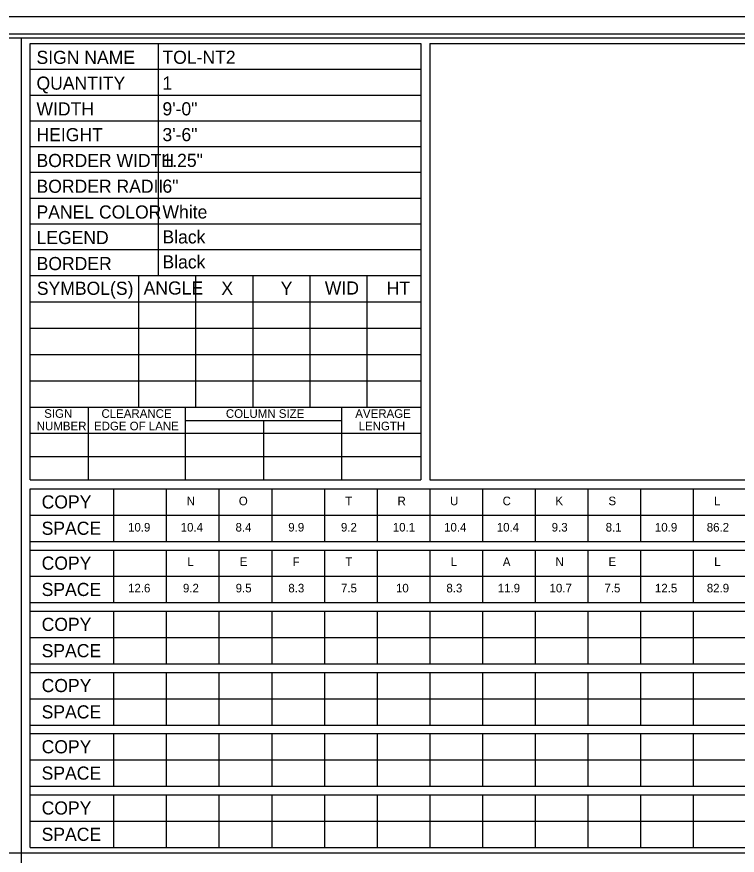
# Model space of a CAD drawing. Extents: x 17890628 to 17890844, y 17897508 to 17897992.
# Drawn here: x 17890772.14 to 17890808.72, y 17897557.55 to 17897600.12 of the extents above; entities that cross this region are included whole.
import ezdxf

# ---------------------------------------------------------------- set-up
doc = ezdxf.new("R2010")
doc.units = 0
for name, color, linetype in [('GSSign', 7, 'Continuous'), ('PlotBorder_dp', 7, 'Continuous'), ('SheetBorder_dp', 7, 'Continuous'), ('SheetLinesMisc2_dp', 7, 'Continuous'), ('TextMinor', 7, 'Continuous')]:
    doc.layers.add(name, color=color, linetype=linetype)

msp = doc.modelspace()

# ---------------------------------------------------------------- linework, layer by layer
at = {"layer": 'PlotBorder_dp'}
msp.add_lwpolyline([(17890700.471, 17897507.741), (17890844.259, 17897507.741), (17890844.259, 17897600.116), (17890700.471, 17897600.116)], close=True, dxfattribs=at)
at = {"layer": 'SheetBorder_dp'}
msp.add_line((17890705.263, 17897599.245), (17890839.466, 17897599.245), dxfattribs=at)
at = {"layer": 'SheetLinesMisc2_dp'}
for p, q in [((17890705.5, 17897599.039), (17890839.233, 17897599.039)), ((17890772.367, 17897599.039), (17890772.367, 17897515.791)), ((17890772.823, 17897576.606), (17890772.823, 17897598.762)), ((17890772.823, 17897598.762), (17890792.654, 17897598.762)), ((17890779.324, 17897598.762), (17890779.324, 17897586.981)), ((17890792.654, 17897598.762), (17890792.654, 17897576.606)), ((17890793.11, 17897598.762), (17890838.594, 17897598.762)), ((17890793.11, 17897598.762), (17890793.11, 17897576.606)), ((17890772.823, 17897597.453), (17890792.654, 17897597.453)), ((17890772.823, 17897596.144), (17890792.654, 17897596.144)), ((17890772.823, 17897594.836), (17890792.654, 17897594.836)), ((17890772.823, 17897593.527), (17890792.654, 17897593.527)), ((17890772.823, 17897592.218), (17890792.654, 17897592.218)), ((17890772.823, 17897590.91), (17890792.654, 17897590.91)), ((17890772.823, 17897589.601), (17890782.738, 17897589.601)), ((17890782.738, 17897589.601), (17890792.654, 17897589.601)), ((17890772.823, 17897588.293), (17890782.738, 17897588.293)), ((17890782.738, 17897588.293), (17890792.654, 17897588.293)), ((17890772.823, 17897586.981), (17890792.654, 17897586.981)), ((17890778.326, 17897586.981), (17890778.326, 17897580.3)), ((17890781.223, 17897586.981), (17890781.223, 17897580.3)), ((17890784.121, 17897586.981), (17890784.121, 17897580.3)), ((17890787.019, 17897586.981), (17890787.019, 17897580.3)), ((17890789.916, 17897586.981), (17890789.916, 17897580.3)), ((17890772.823, 17897585.645), (17890792.654, 17897585.645)), ((17890772.823, 17897584.308), (17890792.654, 17897584.308)), ((17890772.823, 17897582.972), (17890792.654, 17897582.972)), ((17890772.823, 17897581.636), (17890792.654, 17897581.636)), ((17890772.823, 17897580.3), (17890792.654, 17897580.3)), ((17890775.761, 17897580.3), (17890775.761, 17897576.607)), ((17890780.696, 17897580.3), (17890780.696, 17897576.607)), ((17890788.628, 17897580.3), (17890788.628, 17897576.607)), ((17890780.696, 17897579.619), (17890788.628, 17897579.619)), ((17890784.663, 17897579.619), (17890784.663, 17897576.607)), ((17890772.823, 17897578.98), (17890792.654, 17897578.98)), ((17890772.823, 17897577.793), (17890792.654, 17897577.793)), ((17890772.823, 17897576.606), (17890792.654, 17897576.606)), ((17890793.11, 17897576.606), (17890838.594, 17897576.606)), ((17890772.824, 17897557.939), (17890772.824, 17897576.15)), ((17890772.824, 17897576.15), (17890838.594, 17897576.15)), ((17890777.058, 17897576.15), (17890777.058, 17897573.478)), ((17890779.733, 17897576.15), (17890779.733, 17897573.478)), ((17890782.408, 17897576.15), (17890782.408, 17897573.478)), ((17890785.084, 17897576.15), (17890785.084, 17897573.478)), ((17890787.76, 17897576.15), (17890787.76, 17897573.478)), ((17890790.435, 17897576.15), (17890790.435, 17897573.478)), ((17890793.11, 17897576.15), (17890793.11, 17897573.478)), ((17890795.786, 17897576.15), (17890795.786, 17897573.478)), ((17890798.462, 17897576.15), (17890798.462, 17897573.478)), ((17890801.137, 17897576.15), (17890801.137, 17897573.478)), ((17890803.813, 17897576.15), (17890803.813, 17897573.478)), ((17890806.488, 17897576.15), (17890806.488, 17897573.478)), ((17890772.824, 17897574.814), (17890838.594, 17897574.814)), ((17890772.824, 17897573.478), (17890838.594, 17897573.478)), ((17890772.824, 17897573.042), (17890838.594, 17897573.042)), ((17890777.058, 17897573.042), (17890777.058, 17897570.37)), ((17890779.733, 17897573.042), (17890779.733, 17897570.37)), ((17890782.408, 17897573.042), (17890782.408, 17897570.37)), ((17890785.084, 17897573.042), (17890785.084, 17897570.37)), ((17890787.76, 17897573.042), (17890787.76, 17897570.37)), ((17890790.435, 17897573.042), (17890790.435, 17897570.37)), ((17890793.11, 17897573.042), (17890793.11, 17897570.37)), ((17890795.786, 17897573.042), (17890795.786, 17897570.37)), ((17890798.462, 17897573.042), (17890798.462, 17897570.37)), ((17890801.137, 17897573.042), (17890801.137, 17897570.37)), ((17890803.813, 17897573.042), (17890803.813, 17897570.37)), ((17890806.488, 17897573.042), (17890806.488, 17897570.37)), ((17890772.824, 17897571.706), (17890838.594, 17897571.706)), ((17890772.824, 17897570.37), (17890838.594, 17897570.37)), ((17890772.824, 17897569.935), (17890838.594, 17897569.935)), ((17890777.058, 17897569.935), (17890777.058, 17897567.263)), ((17890779.733, 17897569.935), (17890779.733, 17897567.263)), ((17890782.408, 17897569.935), (17890782.408, 17897567.263)), ((17890785.084, 17897569.935), (17890785.084, 17897567.263)), ((17890787.76, 17897569.935), (17890787.76, 17897567.263)), ((17890790.435, 17897569.935), (17890790.435, 17897567.263)), ((17890793.11, 17897569.935), (17890793.11, 17897567.263)), ((17890795.786, 17897569.935), (17890795.786, 17897567.263)), ((17890798.462, 17897569.935), (17890798.462, 17897567.263)), ((17890801.137, 17897569.935), (17890801.137, 17897567.263)), ((17890803.813, 17897569.935), (17890803.813, 17897567.263)), ((17890806.488, 17897569.935), (17890806.488, 17897567.263)), ((17890772.824, 17897568.598), (17890838.594, 17897568.598)), ((17890772.824, 17897567.263), (17890838.594, 17897567.263)), ((17890772.824, 17897566.827), (17890838.594, 17897566.827)), ((17890777.058, 17897566.827), (17890777.058, 17897564.154)), ((17890779.733, 17897566.827), (17890779.733, 17897564.154)), ((17890782.408, 17897566.827), (17890782.408, 17897564.154)), ((17890785.084, 17897566.827), (17890785.084, 17897564.154)), ((17890787.76, 17897566.827), (17890787.76, 17897564.154)), ((17890790.435, 17897566.827), (17890790.435, 17897564.154)), ((17890793.11, 17897566.827), (17890793.11, 17897564.154)), ((17890795.786, 17897566.827), (17890795.786, 17897564.154)), ((17890798.462, 17897566.827), (17890798.462, 17897564.154)), ((17890801.137, 17897566.827), (17890801.137, 17897564.154)), ((17890803.813, 17897566.827), (17890803.813, 17897564.154)), ((17890806.488, 17897566.827), (17890806.488, 17897564.154)), ((17890772.824, 17897565.49), (17890838.594, 17897565.49)), ((17890772.824, 17897564.154), (17890838.594, 17897564.154)), ((17890772.824, 17897563.719), (17890838.594, 17897563.719)), ((17890777.058, 17897563.719), (17890777.058, 17897561.047)), ((17890779.733, 17897563.719), (17890779.733, 17897561.047)), ((17890782.408, 17897563.719), (17890782.408, 17897561.047)), ((17890785.084, 17897563.719), (17890785.084, 17897561.047)), ((17890787.76, 17897563.719), (17890787.76, 17897561.047)), ((17890790.435, 17897563.719), (17890790.435, 17897561.047)), ((17890793.11, 17897563.719), (17890793.11, 17897561.047)), ((17890795.786, 17897563.719), (17890795.786, 17897561.047)), ((17890798.462, 17897563.719), (17890798.462, 17897561.047)), ((17890801.137, 17897563.719), (17890801.137, 17897561.047)), ((17890803.813, 17897563.719), (17890803.813, 17897561.047)), ((17890806.488, 17897563.719), (17890806.488, 17897561.047)), ((17890772.824, 17897562.383), (17890838.594, 17897562.383)), ((17890772.824, 17897561.047), (17890838.594, 17897561.047)), ((17890772.824, 17897560.611), (17890838.594, 17897560.611)), ((17890777.058, 17897560.611), (17890777.058, 17897557.939)), ((17890779.733, 17897560.611), (17890779.733, 17897557.939)), ((17890782.408, 17897560.611), (17890782.408, 17897557.939)), ((17890785.084, 17897560.611), (17890785.084, 17897557.939)), ((17890787.76, 17897560.611), (17890787.76, 17897557.939)), ((17890790.435, 17897560.611), (17890790.435, 17897557.939)), ((17890793.11, 17897560.611), (17890793.11, 17897557.939)), ((17890795.786, 17897560.611), (17890795.786, 17897557.939)), ((17890798.462, 17897560.611), (17890798.462, 17897557.939)), ((17890801.137, 17897560.611), (17890801.137, 17897557.939)), ((17890803.813, 17897560.611), (17890803.813, 17897557.939)), ((17890806.488, 17897560.611), (17890806.488, 17897557.939)), ((17890772.824, 17897559.276), (17890838.594, 17897559.276)), ((17890772.824, 17897557.939), (17890838.594, 17897557.939)), ((17890705.5, 17897557.675), (17890839.233, 17897557.675))]:
    msp.add_line(p, q, dxfattribs=at)

# ---------------------------------------------------------------- texts
at = {"layer": 'GSSign'}
for s, height, p in [('TOL-NT2', 0.6667, (17890779.538, 17897597.727)), ('1', 0.667, (17890779.538, 17897596.418)), ('9\'-0"', 0.6667, (17890779.538, 17897595.109)), ('3\'-6"', 0.6667, (17890779.538, 17897593.801)), ('1.25"', 0.6667, (17890779.538, 17897592.492)), ('6"', 0.6667, (17890779.538, 17897591.183)), ('White', 0.6667, (17890779.538, 17897589.875)), ('Black', 0.6667, (17890779.538, 17897588.606)), ('Black', 0.6667, (17890779.538, 17897587.337)), ('N', 0.436, (17890780.765, 17897575.316)), ('O', 0.436, (17890783.416, 17897575.316)), ('T', 0.436, (17890788.819, 17897575.316)), ('R', 0.436, (17890791.473, 17897575.316)), ('U', 0.436, (17890794.142, 17897575.316)), ('C', 0.436, (17890796.809, 17897575.316)), ('K', 0.436, (17890799.489, 17897575.316)), ('S', 0.436, (17890802.185, 17897575.316)), ('L', 0.436, (17890807.549, 17897575.316)), ('10.9', 0.4357, (17890777.789, 17897573.98)), ('10.4', 0.4357, (17890780.462, 17897573.98)), ('8.4', 0.4357, (17890783.248, 17897573.98)), ('9.9', 0.4357, (17890785.925, 17897573.98)), ('9.2', 0.4357, (17890788.6, 17897573.98)), ('10.1', 0.4357, (17890791.232, 17897573.98)), ('10.4', 0.4357, (17890793.839, 17897573.98)), ('10.4', 0.4357, (17890796.514, 17897573.98)), ('9.3', 0.4357, (17890799.302, 17897573.98)), ('8.1', 0.4357, (17890802.043, 17897573.98)), ('10.9', 0.4357, (17890804.544, 17897573.98)), ('86.2', 0.4357, (17890807.176, 17897573.98)), ('L', 0.436, (17890780.8, 17897572.227)), ('E', 0.436, (17890783.461, 17897572.227)), ('F', 0.436, (17890786.145, 17897572.227)), ('T', 0.436, (17890788.823, 17897572.227)), ('L', 0.436, (17890794.176, 17897572.227)), ('A', 0.436, (17890796.822, 17897572.227)), ('N', 0.436, (17890799.496, 17897572.227)), ('E', 0.436, (17890802.188, 17897572.227)), ('L', 0.436, (17890807.553, 17897572.227)), ('12.6', 0.4357, (17890777.791, 17897570.89)), ('9.2', 0.4357, (17890780.578, 17897570.89)), ('9.5', 0.4357, (17890783.254, 17897570.89)), ('8.3', 0.4357, (17890785.929, 17897570.89)), ('7.5', 0.4357, (17890788.605, 17897570.89)), ('10', 0.4357, (17890791.395, 17897570.89)), ('8.3', 0.4357, (17890793.955, 17897570.89)), ('11.9', 0.4357, (17890796.562, 17897570.89)), ('10.7', 0.4357, (17890799.194, 17897570.89)), ('7.5', 0.4357, (17890801.981, 17897570.89)), ('12.5', 0.4357, (17890804.546, 17897570.89)), ('82.9', 0.4357, (17890807.179, 17897570.89))]:
    msp.add_text(s, height=height, dxfattribs=at).set_placement(p)
at = {"layer": 'TextMinor'}
for s, height, p in [('SIGN NAME', 0.6667, (17890773.142, 17897597.722)), ('QUANTITY', 0.6667, (17890773.142, 17897596.413)), ('WIDTH', 0.6667, (17890773.142, 17897595.104)), ('HEIGHT', 0.6667, (17890773.142, 17897593.796)), ('BORDER WIDTH', 0.66667, (17890773.142, 17897592.487)), ('BORDER RADII', 0.66667, (17890773.142, 17897591.178)), ('PANEL COLOR', 0.66667, (17890773.142, 17897589.87)), ('LEGEND', 0.6667, (17890773.142, 17897588.573)), ('BORDER', 0.6667, (17890773.148, 17897587.253)), ('SYMBOL(S)', 0.6667, (17890773.16, 17897585.998)), ('ANGLE', 0.6667, (17890778.581, 17897586.012)), ('X', 0.667, (17890782.527, 17897585.998)), ('Y', 0.667, (17890785.54, 17897585.998)), ('WID', 0.6667, (17890787.784, 17897586.012)), ('HT', 0.6667, (17890790.925, 17897586)), ('SIGN', 0.4357, (17890773.533, 17897579.755)), ('CLEARANCE', 0.4357, (17890776.44, 17897579.753)), ('COLUMN SIZE', 0.43573, (17890782.758, 17897579.753)), ('AVERAGE', 0.4357, (17890789.33, 17897579.753)), ('NUMBER', 0.4357, (17890773.154, 17897579.121)), ('EDGE OF LANE', 0.43573, (17890776.061, 17897579.121)), ('LENGTH', 0.4357, (17890789.498, 17897579.121)), ('COPY', 0.6667, (17890773.402, 17897575.15)), ('SPACE', 0.6667, (17890773.402, 17897573.814)), ('COPY', 0.6667, (17890773.402, 17897572.043)), ('SPACE', 0.6667, (17890773.402, 17897570.707)), ('COPY', 0.6667, (17890773.402, 17897568.935)), ('SPACE', 0.6667, (17890773.402, 17897567.599)), ('COPY', 0.6667, (17890773.402, 17897565.828)), ('SPACE', 0.6667, (17890773.402, 17897564.491)), ('COPY', 0.6667, (17890773.402, 17897562.719)), ('SPACE', 0.6667, (17890773.402, 17897561.383)), ('COPY', 0.6667, (17890773.402, 17897559.612)), ('SPACE', 0.6667, (17890773.402, 17897558.276))]:
    msp.add_text(s, height=height, dxfattribs=at).set_placement(p)

doc.saveas('drawing.dxf')
